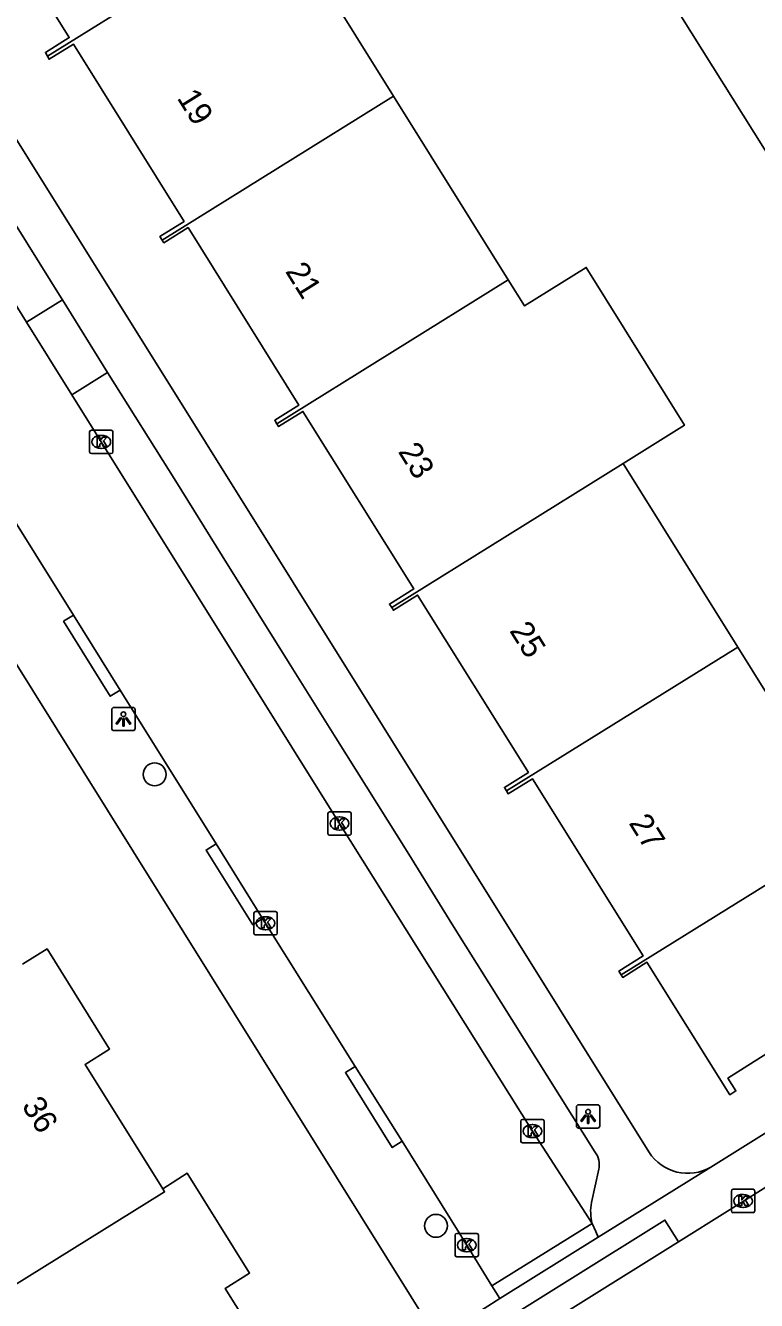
# Model space of a CAD drawing. Extents: x 158838 to 160074, y 386376 to 387776.
# Drawn here: x 159038.5 to 159069.8, y 387055.6 to 387110.2 of the extents above; entities that cross this region are included whole.
import ezdxf

# ---------------------------------------------------------------- set-up
doc = ezdxf.new("R2010")
doc.units = 0
for name, color, linetype in [('IMGEO_Boom', 7, 'Continuous'), ('IMGEO_Kolk', 7, 'Continuous'), ('IMGEO_Lichtpunt', 7, 'Continuous'), ('IMGEO_Pand', 7, 'Continuous'), ('IMGEO_Pand_nummerreeks', 7, 'Continuous'), ('IMGEO_Rijbaan_lokaal_open', 7, 'Continuous'), ('IMGEO_Voetpad_open', 7, 'Continuous')]:
    doc.layers.add(name, color=color, linetype=linetype)

msp = doc.modelspace()

# ---------------------------------------------------------------- linework, layer by layer
at = {"layer": 'IMGEO_Boom'}
for centre in [(159044.044, 387078.122), (159056.092, 387058.799)]:
    msp.add_circle(centre, 0.489, dxfattribs=at)
at = {"layer": 'IMGEO_Kolk'}
for p, q in [((159041.257, 387091.929), (159041.257, 387092.781)), ((159041.332, 387092.855), (159042.184, 387092.855)), ((159041.745, 387092.635), (159041.77, 387092.635)), ((159042.258, 387092.781), (159042.258, 387091.929)), ((159041.768, 387092.075), (159041.743, 387092.075)), ((159042.184, 387091.855), (159041.332, 387091.855)), ((159051.461, 387075.593), (159051.461, 387076.445)), ((159051.536, 387076.519), (159052.388, 387076.519)), ((159051.949, 387076.299), (159051.974, 387076.299)), ((159052.462, 387076.445), (159052.462, 387075.593)), ((159051.972, 387075.739), (159051.947, 387075.739)), ((159052.388, 387075.519), (159051.536, 387075.519)), ((159048.292, 387071.325), (159048.292, 387072.177)), ((159048.367, 387072.251), (159049.219, 387072.251)), ((159048.78, 387072.031), (159048.805, 387072.031)), ((159049.293, 387072.177), (159049.293, 387071.325)), ((159049.219, 387071.251), (159048.367, 387071.251)), ((159048.803, 387071.471), (159048.778, 387071.471)), ((159059.724, 387062.428), (159059.724, 387063.28)), ((159059.799, 387063.354), (159060.651, 387063.354)), ((159060.212, 387063.134), (159060.237, 387063.134)), ((159060.725, 387063.28), (159060.725, 387062.428)), ((159060.235, 387062.574), (159060.21, 387062.574)), ((159060.651, 387062.354), (159059.799, 387062.354)), ((159068.747, 387059.436), (159068.747, 387060.288)), ((159068.822, 387060.362), (159069.674, 387060.362)), ((159069.748, 387060.288), (159069.748, 387059.436)), ((159069.235, 387060.142), (159069.26, 387060.142)), ((159069.674, 387059.362), (159068.822, 387059.362)), ((159069.258, 387059.582), (159069.233, 387059.582)), ((159056.911, 387057.545), (159056.911, 387058.397)), ((159056.986, 387058.471), (159057.838, 387058.471)), ((159057.399, 387058.251), (159057.424, 387058.251)), ((159057.912, 387058.397), (159057.912, 387057.545)), ((159057.422, 387057.691), (159057.397, 387057.691)), ((159057.838, 387057.471), (159056.986, 387057.471))]:
    msp.add_line(p, q, dxfattribs=at)
for points in [[(159041.257, 387091.929), (159041.257, 387092.781)], [(159041.332, 387092.855), (159042.184, 387092.855)], [(159041.578, 387092.555), (159041.701, 387092.555), (159041.701, 387092.404), (159041.831, 387092.555), (159041.995, 387092.555), (159041.849, 387092.404), (159042.002, 387092.155), (159041.85, 387092.155), (159041.765, 387092.319), (159041.701, 387092.252), (159041.701, 387092.155), (159041.578, 387092.155), (159041.578, 387092.555)], [(159042.258, 387092.781), (159042.258, 387091.929)], [(159042.184, 387091.855), (159041.332, 387091.855)], [(159051.461, 387075.593), (159051.461, 387076.445)], [(159051.536, 387076.519), (159052.388, 387076.519)], [(159051.782, 387076.219), (159051.905, 387076.219), (159051.905, 387076.068), (159052.035, 387076.219), (159052.199, 387076.219), (159052.053, 387076.068), (159052.206, 387075.819), (159052.054, 387075.819), (159051.969, 387075.983), (159051.905, 387075.916), (159051.905, 387075.819), (159051.782, 387075.819), (159051.782, 387076.219)], [(159052.462, 387076.445), (159052.462, 387075.593)], [(159052.388, 387075.519), (159051.536, 387075.519)], [(159048.292, 387071.325), (159048.292, 387072.177)], [(159048.367, 387072.251), (159049.219, 387072.251)], [(159048.613, 387071.951), (159048.736, 387071.951), (159048.736, 387071.8), (159048.866, 387071.951), (159049.03, 387071.951), (159048.884, 387071.8), (159049.037, 387071.551), (159048.885, 387071.551), (159048.8, 387071.715), (159048.736, 387071.648), (159048.736, 387071.551), (159048.613, 387071.551), (159048.613, 387071.951)], [(159049.293, 387072.177), (159049.293, 387071.325)], [(159049.219, 387071.251), (159048.367, 387071.251)], [(159059.724, 387062.428), (159059.724, 387063.28)], [(159059.799, 387063.354), (159060.651, 387063.354)], [(159060.045, 387063.054), (159060.168, 387063.054), (159060.168, 387062.903), (159060.298, 387063.054), (159060.462, 387063.054), (159060.316, 387062.903), (159060.469, 387062.654), (159060.317, 387062.654), (159060.232, 387062.818), (159060.168, 387062.751), (159060.168, 387062.654), (159060.045, 387062.654), (159060.045, 387063.054)], [(159060.725, 387063.28), (159060.725, 387062.428)], [(159060.651, 387062.354), (159059.799, 387062.354)], [(159068.747, 387059.436), (159068.747, 387060.288)], [(159068.822, 387060.362), (159069.674, 387060.362)], [(159069.748, 387060.288), (159069.748, 387059.436)], [(159069.068, 387060.062), (159069.191, 387060.062), (159069.191, 387059.911), (159069.321, 387060.062), (159069.485, 387060.062), (159069.339, 387059.911), (159069.492, 387059.662), (159069.34, 387059.662), (159069.255, 387059.826), (159069.191, 387059.759), (159069.191, 387059.662), (159069.068, 387059.662), (159069.068, 387060.062)], [(159069.674, 387059.362), (159068.822, 387059.362)], [(159056.911, 387057.545), (159056.911, 387058.397)], [(159056.986, 387058.471), (159057.838, 387058.471)], [(159057.232, 387058.171), (159057.355, 387058.171), (159057.355, 387058.02), (159057.485, 387058.171), (159057.649, 387058.171), (159057.503, 387058.02), (159057.656, 387057.771), (159057.504, 387057.771), (159057.419, 387057.935), (159057.355, 387057.868), (159057.355, 387057.771), (159057.232, 387057.771), (159057.232, 387058.171)], [(159057.912, 387058.397), (159057.912, 387057.545)], [(159057.838, 387057.471), (159056.986, 387057.471)]]:
    msp.add_lwpolyline(points, dxfattribs=at)
for centre, start, end in [((159041.334, 387092.779), 91.552, 178.448), ((159041.334, 387092.779), 91.552, 178.448), ((159042.182, 387092.779), 1.552, 88.448), ((159042.182, 387092.779), 1.552, 88.448), ((159041.334, 387091.931), 181.552, 268.448), ((159041.334, 387091.931), 181.552, 268.448), ((159042.182, 387091.931), 271.552, 358.448), ((159042.182, 387091.931), 271.552, 358.448), ((159051.538, 387076.443), 91.552, 178.448), ((159051.538, 387076.443), 91.552, 178.448), ((159052.386, 387076.443), 1.552, 88.448), ((159052.386, 387076.443), 1.552, 88.448), ((159051.538, 387075.595), 181.552, 268.448), ((159051.538, 387075.595), 181.552, 268.448), ((159052.386, 387075.595), 271.552, 358.448), ((159052.386, 387075.595), 271.552, 358.448), ((159048.369, 387072.175), 91.552, 178.448), ((159048.369, 387072.175), 91.552, 178.448), ((159049.217, 387072.175), 1.552, 88.448), ((159049.217, 387072.175), 1.552, 88.448), ((159048.369, 387071.327), 181.552, 268.448), ((159048.369, 387071.327), 181.552, 268.448), ((159049.217, 387071.327), 271.552, 358.448), ((159049.217, 387071.327), 271.552, 358.448), ((159059.801, 387063.278), 91.552, 178.448), ((159059.801, 387063.278), 91.552, 178.448), ((159060.649, 387063.278), 1.552, 88.448), ((159060.649, 387063.278), 1.552, 88.448), ((159059.801, 387062.43), 181.552, 268.448), ((159059.801, 387062.43), 181.552, 268.448), ((159060.649, 387062.43), 271.552, 358.448), ((159060.649, 387062.43), 271.552, 358.448), ((159068.824, 387060.286), 91.552, 178.448), ((159068.824, 387060.286), 91.552, 178.448), ((159069.672, 387060.286), 1.552, 88.448), ((159069.672, 387060.286), 1.552, 88.448), ((159068.824, 387059.438), 181.552, 268.448), ((159068.824, 387059.438), 181.552, 268.448), ((159069.672, 387059.438), 271.552, 358.448), ((159069.672, 387059.438), 271.552, 358.448), ((159056.988, 387058.395), 91.552, 178.448), ((159056.988, 387058.395), 91.552, 178.448), ((159057.836, 387058.395), 1.552, 88.448), ((159057.836, 387058.395), 1.552, 88.448), ((159056.988, 387057.547), 181.552, 268.448), ((159056.988, 387057.547), 181.552, 268.448), ((159057.836, 387057.547), 271.552, 358.448), ((159057.836, 387057.547), 271.552, 358.448)]:
    msp.add_arc(centre, 0.0765, start, end, dxfattribs=at)
for centre, major_axis, ratio, start_param, end_param in [((159041.744, 387092.355), (-0.387, 0.002), 0.722429, 4.712389, 7.853982), ((159041.769, 387092.355), (-0.39, 0.002), 0.717154, 1.570796, 4.712389), ((159051.948, 387076.019), (-0.387, 0.002), 0.722429, 4.712389, 7.853982), ((159051.973, 387076.019), (-0.39, 0.002), 0.717154, 1.570796, 4.712389), ((159048.779, 387071.751), (-0.387, 0.002), 0.722429, 4.712389, 7.853982), ((159048.804, 387071.751), (-0.39, 0.002), 0.717154, 1.570796, 4.712389), ((159060.211, 387062.854), (-0.387, 0.002), 0.722429, 4.712389, 7.853982), ((159060.236, 387062.854), (-0.39, 0.002), 0.717154, 1.570796, 4.712389), ((159069.234, 387059.862), (-0.387, 0.002), 0.722429, 4.712389, 7.853982), ((159069.259, 387059.862), (-0.39, 0.002), 0.717154, 1.570796, 4.712389), ((159057.398, 387057.971), (-0.387, 0.002), 0.722429, 4.712389, 7.853982), ((159057.423, 387057.971), (-0.39, 0.002), 0.717154, 1.570796, 4.712389)]:
    msp.add_ellipse(centre, major_axis=major_axis, ratio=ratio, start_param=start_param, end_param=end_param, dxfattribs=at)
at = {"layer": 'IMGEO_Lichtpunt'}
for p, q in [((159042.208, 387080.896), (159042.208, 387080.089)), ((159042.208, 387080.896), (159042.208, 387080.089)), ((159043.11, 387080.991), (159042.302, 387080.991)), ((159043.11, 387080.991), (159042.302, 387080.991)), ((159043.204, 387080.089), (159043.204, 387080.896)), ((159043.204, 387080.089), (159043.204, 387080.896)), ((159042.302, 387079.995), (159043.11, 387079.995)), ((159042.302, 387079.995), (159043.11, 387079.995)), ((159062.11, 387063.885), (159062.11, 387063.078)), ((159062.11, 387063.885), (159062.11, 387063.078)), ((159063.012, 387063.98), (159062.204, 387063.98)), ((159063.012, 387063.98), (159062.204, 387063.98)), ((159063.106, 387063.078), (159063.106, 387063.885)), ((159063.106, 387063.078), (159063.106, 387063.885)), ((159062.204, 387062.984), (159063.012, 387062.984)), ((159062.204, 387062.984), (159063.012, 387062.984))]:
    msp.add_line(p, q, dxfattribs=at)
for points in [[(159042.582, 387080.56), (159042.621, 387080.532), (159042.433, 387080.27), (159042.395, 387080.297), (159042.582, 387080.56)], [(159042.684, 387080.512), (159042.731, 387080.512), (159042.731, 387080.19), (159042.684, 387080.19), (159042.684, 387080.512)], [(159042.794, 387080.532), (159042.832, 387080.559), (159043.019, 387080.297), (159042.98, 387080.269), (159042.794, 387080.532)], [(159062.484, 387063.549), (159062.523, 387063.521), (159062.335, 387063.259), (159062.297, 387063.286), (159062.484, 387063.549)], [(159062.586, 387063.501), (159062.633, 387063.501), (159062.633, 387063.179), (159062.586, 387063.179), (159062.586, 387063.501)], [(159062.696, 387063.521), (159062.734, 387063.548), (159062.921, 387063.286), (159062.882, 387063.258), (159062.696, 387063.521)]]:
    msp.add_lwpolyline(points, dxfattribs=at)
for centre in [(159042.707, 387080.694), (159062.609, 387063.683)]:
    msp.add_circle(centre, 0.0994, dxfattribs=at)
for centre, start, end in [((159042.302, 387080.896), 90, 180), ((159042.302, 387080.896), 90, 180), ((159043.11, 387080.896), 0, 90), ((159043.11, 387080.896), 0, 90), ((159042.302, 387080.089), 180, 270), ((159042.302, 387080.089), 180, 270), ((159043.11, 387080.089), 270, 0), ((159043.11, 387080.089), 270, 360), ((159062.204, 387063.885), 90, 180), ((159062.204, 387063.885), 90, 180), ((159063.012, 387063.885), 0, 90), ((159063.012, 387063.885), 0, 90), ((159062.204, 387063.078), 180, 270), ((159062.204, 387063.078), 180, 270), ((159063.012, 387063.078), 270, 0), ((159063.012, 387063.078), 270, 360)]:
    msp.add_arc(centre, 0.0946, start, end, dxfattribs=at)
at = {"layer": 'IMGEO_Pand'}
for points in [[(159039.451, 387108.863), (159039.362, 387109.024), (159040.387, 387109.664), (159035.646, 387117.247), (159034.6, 387116.593), (159034.518, 387116.723)], [(159039.451, 387108.863), (159049.358, 387115.031)], [(159049.358, 387115.031), (159054.275, 387107.16)], [(159044.366, 387100.989), (159044.266, 387101.145), (159045.306, 387101.795), (159040.561, 387109.385), (159039.522, 387108.735), (159039.451, 387108.863)], [(159054.275, 387107.16), (159044.366, 387100.989)], [(159054.275, 387107.16), (159059.186, 387099.298)], [(159049.28, 387093.13), (159049.184, 387093.279), (159050.224, 387093.929), (159045.475, 387101.525), (159044.438, 387100.877), (159044.366, 387100.989)], [(159059.186, 387099.298), (159059.887, 387098.177), (159062.529, 387099.822), (159066.736, 387093.064), (159064.104, 387091.426)], [(159049.28, 387093.13), (159059.186, 387099.298)], [(159054.199, 387085.26), (159054.1, 387085.411), (159055.141, 387086.062), (159050.391, 387093.66), (159049.355, 387093.012), (159049.28, 387093.13)], [(159064.104, 387091.426), (159054.199, 387085.26)], [(159064.104, 387091.426), (159069.015, 387083.564)], [(159059.111, 387077.412), (159059.022, 387077.562), (159060.053, 387078.206), (159055.307, 387085.798), (159054.271, 387085.15), (159054.199, 387085.26)], [(159059.111, 387077.412), (159069.015, 387083.564)], [(159069.015, 387083.564), (159073.932, 387075.693)], [(159064.021, 387069.549), (159063.927, 387069.706), (159064.962, 387070.353), (159060.221, 387077.938), (159059.184, 387077.29), (159059.111, 387077.412)], [(159073.932, 387075.693), (159077.921, 387069.308), (159073.386, 387066.475), (159072.636, 387067.668), (159068.594, 387065.126), (159068.939, 387064.576), (159068.677, 387064.411), (159065.13, 387070.084), (159064.091, 387069.434), (159064.021, 387069.549)], [(159073.932, 387075.693), (159064.021, 387069.549)], [(159038.384, 387069.996), (159039.435, 387070.652), (159042.114, 387066.367), (159041.062, 387065.709), (159044.387, 387060.389)], [(159044.387, 387060.389), (159045.439, 387061.047), (159048.113, 387056.775), (159047.067, 387056.119), (159050.577, 387050.525)], [(159036.538, 387055.521), (159036.623, 387055.385), (159044.472, 387060.253), (159044.387, 387060.389)]]:
    msp.add_lwpolyline(points, dxfattribs=at)
at = {"layer": 'IMGEO_Rijbaan_lokaal_open'}
for points in [[(159050.036, 387137.339), (159059.646, 387121.563), (159061.621, 387118.5), (159070.62, 387104.158)], [(159066.482, 387058.108), (159085.362, 387069.926), (159087.209, 387071.089), (159090.415, 387073.084), (159104.81, 387082.095), (159121.021, 387092.233), (159137.382, 387102.443), (159140.304, 387104.262)], [(159038.554, 387097.483), (159035.596, 387102.225)], [(159040.497, 387094.367), (159038.554, 387097.483)], [(159062.785, 387058.895), (159060.22, 387062.853), (159051.957, 387076.019), (159041.753, 387092.354), (159040.497, 387094.367)], [(159040.565, 387084.943), (159037.331, 387090.108), (159036.688, 387091.164)], [(159040.565, 387084.943), (159042.564, 387081.727)], [(159046.674, 387075.143), (159042.564, 387081.727)], [(159046.674, 387075.143), (159048.667, 387071.949)], [(159052.636, 387065.62), (159048.667, 387071.949)], [(159052.636, 387065.62), (159054.64, 387062.416)], [(159058.484, 387056.236), (159057.409, 387057.972), (159054.64, 387062.416)], [(159058.484, 387056.236), (159062.785, 387058.895)], [(159062.785, 387058.895), (159062.935, 387058.551), (159063.036, 387058.319)], [(159066.482, 387058.108), (159057.993, 387052.813)], [(159063.036, 387058.319), (159058.826, 387055.683)], [(159058.826, 387055.683), (159058.484, 387056.236)]]:
    msp.add_lwpolyline(points, dxfattribs=at)
at = {"layer": 'IMGEO_Voetpad_open'}
for points in [[(159056.14, 387053.974), (159008.415, 387130.408), (159005.915, 387134.425)], [(159023.399, 387128.857), (159065.214, 387061.96)], [(159037.124, 387103.178), (159040.035, 387098.527), (159040.092, 387098.435)], [(159038.554, 387097.483), (159040.092, 387098.435)], [(159040.092, 387098.435), (159042.022, 387095.318)], [(159042.022, 387095.318), (159040.497, 387094.367)], [(159042.022, 387095.318), (159044.952, 387090.668), (159046.941, 387087.475), (159049.806, 387082.887), (159051.799, 387079.687), (159054.854, 387074.815), (159056.85, 387071.612), (159062.903, 387061.966)], [(159042.564, 387081.727), (159042.14, 387081.464), (159040.141, 387084.68), (159040.565, 387084.943)], [(159048.667, 387071.949), (159048.243, 387071.685), (159046.25, 387074.879), (159046.674, 387075.143)], [(159067.868, 387061.308), (159078.525, 387067.969), (159086.674, 387073.064), (159089.207, 387074.648)], [(159054.64, 387062.416), (159054.217, 387062.151), (159052.213, 387065.355), (159052.636, 387065.62)], [(159063.064, 387061.217), (159062.751, 387059.797)], [(159067.868, 387061.308), (159063.036, 387058.319)], [(159057.993, 387052.813), (159057.411, 387053.746), (159065.9, 387059.041), (159066.482, 387058.108)], [(159058.826, 387055.683), (159056.14, 387053.974)]]:
    msp.add_lwpolyline(points, dxfattribs=at)
for centre, radius, start, end in [((159062.184, 387061.42), 0.903, 347.0196, 37.2431), ((159066.882, 387063.023), 1.978, 212.5003, 299.895), ((159064.777, 387059.422), 2.06, 169.5051, 194.8123)]:
    msp.add_arc(centre, radius, start, end, dxfattribs=at)

# ---------------------------------------------------------------- texts
at = {"layer": 'IMGEO_Pand_nummerreeks'}
for s, rotation, p in [('19', 302.0118, (159044.977, 387107.076)), ('21', 302.0118, (159049.616, 387099.656)), ('23', 302.0118, (159054.446, 387091.941)), ('25', 302.0118, (159059.218, 387084.273)), ('27', 302.0118, (159064.328, 387076.041)), ('36', 302.0069, (159038.327, 387063.935))]:
    msp.add_text(s, height=1, rotation=rotation, dxfattribs=at).set_placement(p)

doc.saveas('drawing.dxf')
